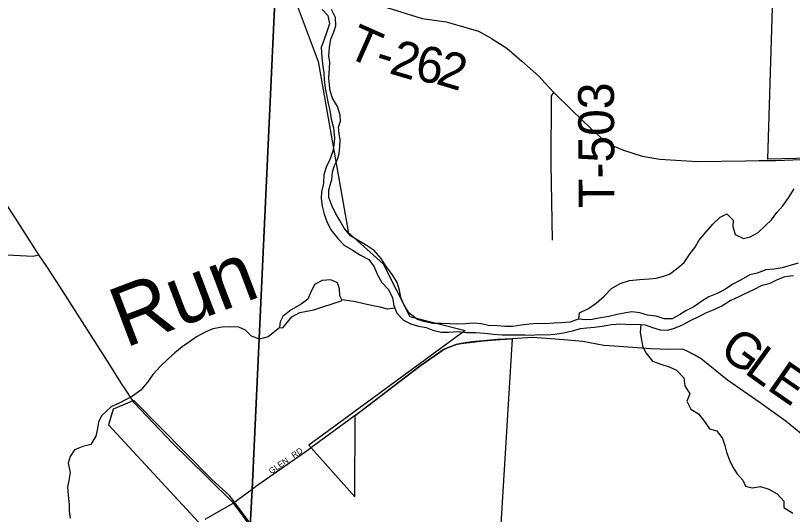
# Model space of a CAD drawing. Extents: x 1759416 to 2214760, y 252598 to 1116833.
# Drawn here: x 1975170 to 1981672, y 862305 to 866477 of the extents above; entities that cross this region are included whole.
import ezdxf

# ---------------------------------------------------------------- set-up
doc = ezdxf.new("R2010")
doc.units = 0
for name, color, linetype in [('GM_X_City_Street', 7, 'Continuous'), ('GM_X_City_Street_Text', 7, 'Continuous'), ('GM_X_Corporation', 7, 'Continuous'), ('GM_X_Major_River', 7, 'Continuous'), ('GM_X_Minor_Lake', 7, 'Continuous'), ('GM_X_Minor_River', 7, 'Continuous'), ('GM_X_Minor_River_Text', 7, 'Continuous'), ('GM_X_State_Route', 7, 'Continuous'), ('GM_X_Township', 7, 'Continuous'), ('GM_X_Township_Road', 7, 'Continuous'), ('GM_X_Township_Road_Text', 7, 'Continuous')]:
    doc.layers.add(name, color=color, linetype=linetype)

msp = doc.modelspace()

# ---------------------------------------------------------------- linework, layer by layer
at = {"layer": 'GM_X_City_Street'}
for points in [[(1973492.8, 864560.1), (1975315.2, 864464.9), (1975365.5, 864474.9)], [(1977670.5, 862880.7), (1977621.5, 862844.7), (1977179.2, 862535.3), (1977150.5, 862514.3), (1976994.5, 862400.2)]]:
    msp.add_lwpolyline(points, dxfattribs=at)
at = {"layer": 'GM_X_Corporation'}
for points in [[(1977201.2, 867433.9), (1977703.7, 866093.8), (1977954.6, 864670.3), (1977948.2, 864668.6), (1978245.5, 864400.9), (1978470.2, 863959.8), (1978933.1, 863844.4), (1977624.9, 862885.5), (1978010.8, 862453.3), (1978013.5, 863132.2), (1978553.3, 863543.7), (1978756.9, 863686.4), (1978856.5, 863726.6), (1978899.6, 863735.5), (1979084.1, 863756.2), (1979224.8, 863766.6), (1979325.1, 863774.1), (1979214, 861950.5)], [(1982067, 865290.6), (1981467.1, 865274.9), (1981506.1, 866543.4)], [(1977179.8, 862167.4), (1976961, 862462.6), (1976811.9, 862597.2), (1976160.8, 863258), (1975987.3, 863186.5), (1975947.8, 863054.3), (1976704, 862236.7)]]:
    msp.add_lwpolyline(points, dxfattribs=at)
at = {"layer": 'GM_X_Major_River'}
for points in [[(1977735.1, 866528.4), (1977783.1, 866476.2), (1977797, 866407.9), (1977774.8, 866339.8), (1977752.6, 866275.6), (1977728.4, 866209.4), (1977732.2, 866125.1), (1977742.1, 866050.9), (1977750, 865998.7), (1977753.9, 865942.5), (1977761.8, 865870.2), (1977771.7, 865814.1), (1977787.6, 865741.8), (1977799.6, 865685.6), (1977811.5, 865609.3), (1977831.4, 865539.1), (1977839.2, 865450.8), (1977835.1, 865392.6), (1977825, 865342.4), (1977800.7, 865272.2), (1977770.5, 865210.1), (1977750.3, 865145.9), (1977747.3, 865079.3)], [(1977816.4, 865103.7), (1977822.6, 865169.9), (1977838.8, 865222), (1977864.9, 865272.2), (1977877.1, 865322.3), (1977883.2, 865380.5), (1977887.4, 865436.6), (1977879.4, 865490.8), (1977873.5, 865543), (1977889.7, 865593.2), (1977887.8, 865645.3), (1977863.8, 865715.6), (1977823.8, 865785.9), (1977803.9, 865846.1), (1977798, 865896.3), (1977792.1, 865952.5), (1977796.3, 866034.7), (1977800.4, 866084.9), (1977792.5, 866141.1), (1977796.6, 866209.3), (1977808.8, 866279.5), (1977831, 866331.6), (1977849.2, 866389.8), (1977847.3, 866460), (1977813.3, 866526.3)], [(1981719.7, 864407.1), (1981651.7, 864387.1), (1981585.7, 864367.2), (1981517.7, 864357.2), (1981447.8, 864349.3), (1981375.8, 864321.4), (1981313.8, 864307.4), (1981243.8, 864267.4), (1981173.8, 864231.5), (1981111.8, 864189.5), (1981041.8, 864151.5), (1980971.8, 864123.5), (1980913.8, 864087.5), (1980847.8, 864041.5), (1980779.8, 864007.5), (1980727.8, 863973.5), (1980663.8, 863939.5), (1980597.9, 863939.6), (1980531.9, 863961.8), (1980458, 863971.9), (1980394.1, 863990), (1980328.1, 863998.2), (1980276.2, 863990.2), (1980206.2, 863978.3), (1980134.2, 863960.3), (1980066.3, 863948.4), (1979996.3, 863934.5), (1979944.3, 863932.6), (1979878.4, 863938.7), (1979810.4, 863912.7), (1979740.4, 863906.8), (1979674.5, 863904.9), (1979610.5, 863898.9), (1979536.6, 863903.1), (1979472.6, 863897.2), (1979402.6, 863887.2), (1979328.7, 863877.3), (1979264.7, 863875.4), (1979200.8, 863881.5), (1979128.8, 863885.6), (1979066.9, 863897.7), (1979002.9, 863903.8), (1978935, 863897.9), (1978863, 863896), (1978805.1, 863900.1), (1978731.1, 863902.2), (1978663.2, 863902.3), (1978599.2, 863914.4), (1978535.3, 863936.6), (1978465.4, 863988.8), (1978423.5, 864055), (1978395.6, 864119.2), (1978383.7, 864181.3), (1978363.8, 864243.5), (1978323.9, 864307.7), (1978272, 864377.9), (1978230.1, 864446.1), (1978172.3, 864512.3), (1978104.4, 864556.5), (1978038.5, 864594.7), (1977974.6, 864634.9), (1977920.7, 864699.1), (1977884.8, 864763.3), (1977848.9, 864825.5), (1977817, 864889.7), (1977793.1, 864955.8), (1977791.7, 865016.9), (1977810.2, 865088.6), (1977816.4, 865103.7)], [(1977747.3, 865079.3), (1977743.2, 865062.1), (1977731.2, 865002), (1977729.1, 864947.9), (1977735, 864881.8), (1977752.9, 864815.6), (1977776.8, 864747.4), (1977810.7, 864683.2), (1977866.6, 864613), (1977922.5, 864554.8), (1977986.4, 864516.6), (1978058.3, 864474.4), (1978126.2, 864436.2), (1978172.1, 864376), (1978198, 864309.8), (1978235.9, 864245.7), (1978291.8, 864187.4), (1978325.7, 864117.2), (1978335.6, 864051.1), (1978361.5, 863988.9), (1978417.4, 863930.7), (1978477.3, 863898.6), (1978543.2, 863878.4), (1978607.2, 863868.3), (1978661.1, 863846.2), (1978733, 863828), (1978797, 863830), (1978869, 863833.9), (1978942.9, 863827.7), (1979022.8, 863825.6), (1979098.8, 863821.5), (1979166.7, 863813.4), (1979242.7, 863807.3), (1979432.5, 863807), (1979484.5, 863804.9), (1979548.4, 863808.8), (1979618.4, 863806.8), (1979682.4, 863812.7), (1979756.3, 863822.6), (1979830.3, 863840.5), (1979898.3, 863860.5), (1979952.2, 863866.4), (1980014.2, 863870.3), (1980080.2, 863878.2), (1980156.1, 863892.2), (1980236.1, 863898.1), (1980312, 863893.9), (1980372, 863895.9), (1980437.9, 863889.8), (1980501.9, 863869.6), (1980565.8, 863847.5), (1980627.7, 863845.4), (1980683.7, 863863.4), (1980751.7, 863889.3), (1980819.7, 863927.3), (1980889.7, 863959.3), (1980947.7, 863991.3), (1981017.7, 864019.2), (1981081.7, 864049.2), (1981149.7, 864093.2), (1981213.7, 864123.2), (1981269.7, 864149.2), (1981349.7, 864185.1), (1981419.6, 864221.1), (1981485.6, 864239), (1981547.6, 864269), (1981611.6, 864295), (1981681.6, 864302.9)]]:
    msp.add_lwpolyline(points, dxfattribs=at)
at = {"layer": 'GM_X_Minor_Lake'}
for points in [[(1977902.5, 864094.6), (1977884.7, 864132.8), (1977881.1, 864193), (1977863.3, 864243.2), (1977809.5, 864265.6), (1977737.4, 864260), (1977673.3, 864228.3), (1977638.9, 864158.3), (1977616.7, 864104.3), (1977560.4, 864064.5), (1977476.2, 864014.8), (1977407.9, 863959.1), (1977383.7, 863915.1), (1977379.5, 863869), (1977407.4, 863864.8), (1977481.9, 863958.7), (1977548.1, 863994.4), (1977666.2, 864015.7)], [(1977666.2, 864015.7), (1977902.5, 864094.6)]]:
    msp.add_lwpolyline(points, dxfattribs=at)
at = {"layer": 'GM_X_Minor_River'}
for points in [[(1979884.7, 863938.1), (1979889.6, 863990.6), (1979965.7, 864026.2), (1980028, 864072), (1980096.3, 864129.8), (1980158.6, 864195.6), (1980230.8, 864237.2), (1980306.9, 864260.9), (1980392.9, 864270.4), (1980472.9, 864273.9), (1980531, 864279.6), (1980585, 864295.3), (1980643.1, 864313), (1980713.4, 864366.8), (1980765.6, 864412.6), (1980816, 864488.5), (1980858.3, 864540.4), (1980888.6, 864596.4), (1980950.9, 864668.2), (1981005.3, 864732.1), (1981067.6, 864791.9), (1981121.7, 864817.6), (1981175.4, 864767.2), (1981173.1, 864713), (1981192.8, 864644.7), (1981262.6, 864612.2), (1981318.6, 864625.9), (1981384.8, 864663.7), (1981443.1, 864717.4), (1981495.4, 864769.3), (1981541.7, 864829.2), (1981589.9, 864885.1), (1981638.3, 864953), (1981686.7, 865028.9)], [(1978344.9, 864028.8), (1978284.1, 864022.1), (1978220.2, 864038.5), (1978162.2, 864048.9), (1978084.4, 864067.4), (1978014.5, 864083.9), (1977944.5, 864094.3), (1977900.2, 864099.6)], [(1977381.7, 863868.7), (1977283.1, 863791.4), (1977213, 863771.7), (1977145.1, 863796.2), (1977093.4, 863846.6), (1977037.5, 863871), (1976961.6, 863873.5), (1976899.6, 863869.8), (1976821.5, 863856.3), (1976763.4, 863832.5), (1976683.2, 863788.9), (1976625, 863749.1), (1976564.8, 863707.3), (1976502.5, 863657.6), (1976448.3, 863605.7), (1976382, 863546), (1976319.6, 863474.1), (1976273.3, 863412.2), (1976218.9, 863344.4), (1976148.7, 863294.6), (1976096.5, 863264.9), (1976038.4, 863235.1), (1975970.2, 863205.4), (1975891.9, 863133.7), (1975865.6, 863079.7), (1975855.3, 863023.6), (1975841, 862959.5), (1975800.6, 862889.5), (1975734.5, 862871.9), (1975662.4, 862846.2), (1975626.1, 862790.3), (1975609.8, 862734.2), (1975627.4, 862655.9), (1975617, 862587.8), (1975604.8, 862533.7), (1975610.4, 862467.5), (1975618, 862389.2), (1975619.7, 862331.1), (1975627.4, 862274.9)], [(1980402.8, 863893), (1980398.6, 863827.1), (1980408.3, 863764.9), (1980418, 863714.7), (1980443.7, 863656.4), (1980499.3, 863587.9), (1980569.1, 863561.4), (1980639, 863538.9), (1980700.9, 863512.5), (1980762.5, 863447.9), (1980772.2, 863381.7), (1980811.8, 863313.2), (1980787.5, 863253.2), (1980821.1, 863184.8), (1980886.9, 863146.3), (1980934.5, 863081.9), (1980976.2, 863021.5), (1981040.1, 863005), (1981085.7, 862940.6), (1981105.4, 862880.3), (1981119.1, 862826.1), (1981144.8, 862757.7), (1981170.5, 862705.4), (1981206.2, 862647.1), (1981255.9, 862592.6), (1981279.6, 862542.3), (1981335.5, 862528), (1981405.5, 862537.6), (1981473.4, 862515.1), (1981545.2, 862476.6), (1981598.9, 862416.1), (1981598.6, 862363.9), (1981676.3, 862315.4)]]:
    msp.add_lwpolyline(points, dxfattribs=at)
at = {"layer": 'GM_X_State_Route'}
for points in [[(1975431.9, 864377.9), (1975365.5, 864474.9), (1975164.5, 864791.7), (1974968.7, 865084.5), (1974773.6, 865392.5), (1974543.2, 865759.6), (1974445.1, 865914.2), (1974302.6, 866066.5), (1974028.4, 866389.5), (1973764.1, 866773.9), (1973334, 867326), (1973203.6, 867497.5)], [(1975540.9, 864211.7), (1975474.5, 864315.7), (1975431.9, 864377.9)], [(1976075.1, 863373.4), (1976071.8, 863378.6), (1975939.5, 863587.3), (1975540.9, 864211.7)], [(1976994.5, 862400.2), (1976774.4, 862617.4), (1976484.4, 862900.6), (1976163.1, 863238.3), (1976075.1, 863373.4)], [(1977777.4, 861576.2), (1977675.6, 861615.2), (1977596.3, 861663.7), (1977492.7, 861733.2), (1977418.9, 861799.4), (1977351.1, 861886.8), (1977267.2, 862012), (1977133.4, 862207.4), (1977072.6, 862296), (1976994.5, 862400.2)]]:
    msp.add_lwpolyline(points, dxfattribs=at)
at = {"layer": 'GM_X_Township'}
for points in [[(1977495.1, 869420.8), (1977468.9, 869117.6), (1977456.6, 868931.3), (1977397.8, 868003.6), (1977388.2, 867910.1), (1977396.5, 867802.9), (1977150.5, 862514.3), (1977133.4, 862207.4), (1977036.1, 860466.3), (1977005.6, 859919.9), (1976964.7, 859186.8), (1976931.3, 858590.2), (1976934.2, 858551.6), (1976926.5, 858367.3), (1976916.9, 858304.6), (1976913.8, 858097.3), (1976901.3, 857970.1), (1976894.3, 857823.9), (1976893.3, 857773.7), (1976896.4, 857732.8), (1976716.8, 854704.7)], [(1976716.8, 854704.7), (1976896.4, 857732.8), (1976893.3, 857773.7), (1976894.3, 857823.9), (1976901.3, 857970.1), (1976913.8, 858097.3), (1976916.9, 858304.6), (1976926.5, 858367.3), (1976934.2, 858551.6), (1976931.3, 858590.2), (1976964.7, 859186.8), (1977005.6, 859919.9), (1977036.1, 860466.3), (1977133.4, 862207.4), (1977150.5, 862514.3), (1977396.5, 867802.9), (1977388.2, 867910.1), (1977397.8, 868003.6), (1977456.6, 868931.3), (1977468.9, 869117.6), (1977495.1, 869420.8)]]:
    msp.add_lwpolyline(points, dxfattribs=at)
at = {"layer": 'GM_X_Township_Road'}
for points in [[(1977631.8, 867201.2), (1977675.8, 867119.1), (1977729.2, 867012.3), (1977820.2, 866881.8), (1977940.7, 866769.1), (1978059.3, 866660.3), (1978233.9, 866559.5), (1978572.4, 866452.5), (1978774.1, 866424.6), (1978872.9, 866396.1), (1979045.5, 866345.8), (1979149.5, 866288.8), (1979153.9, 866285.9)], [(1979153.9, 866285.9), (1979280.2, 866203.3), (1979405.9, 866096), (1979550, 865970.3), (1979603.3, 865912.7)], [(1979603.3, 865912.7), (1979675.7, 865834.5), (1979828.2, 865683.7), (1979984, 865531.1), (1980067.8, 865457.4), (1980178.4, 865383.6), (1980257.2, 865351.7), (1980413.8, 865301.8), (1980563.3, 865276), (1980873.2, 865256.3), (1981277.9, 865262.2), (1981389.2, 865263.8), (1981422.5, 865264.3)], [(1979663.9, 864597.6), (1979653.9, 865239.4), (1979655.6, 865804.4), (1979675.7, 865834.5)], [(1981422.5, 865264.3), (1981532.3, 865265.9), (1982031.3, 865283.5), (1982120.1, 865289.6), (1982155.2, 865292.1)], [(1978950.3, 863741.8), (1978899.6, 863735.5), (1978856.5, 863726.6), (1978756.9, 863686.4), (1978553.3, 863543.7), (1978051.6, 863160.2), (1978013.5, 863132.2), (1977963.2, 863095.3)], [(1979208.3, 863767), (1979204.3, 863766.7), (1979084.1, 863756.1), (1979018.5, 863750.4), (1978950.3, 863741.8)], [(1981758.4, 862967.9), (1981620.4, 863083.6), (1981401.4, 863237.8), (1981129.5, 863428.5), (1980907.9, 863605.4), (1980854, 863637.3), (1980797.6, 863668), (1980751, 863686.4), (1980635.9, 863685.1), (1980487.7, 863688.8), (1980220.5, 863709.4), (1980093.3, 863719.1), (1979917.9, 863750.4), (1979760.3, 863765.3), (1979497.2, 863784.6), (1979325.1, 863774.1), (1979208.3, 863767)], [(1977963.2, 863095.3), (1977670.5, 862880.7)], [(1976994.5, 862400.2), (1976755.2, 862263.9)]]:
    msp.add_lwpolyline(points, dxfattribs=at)

# ---------------------------------------------------------------- texts
at = {"layer": 'GM_X_City_Street_Text'}
for s, rotation, p in [('RD', 34.50504, (1977500.7, 862772.2)), ('GLEN', 34.98957, (1977311.4, 862640.2))]:
    msp.add_text(s, height=50, rotation=rotation, dxfattribs=at).set_placement(p)
at = {"layer": 'GM_X_Minor_River_Text'}
msp.add_text('Run', height=500.03, rotation=20.80874, dxfattribs=at).set_placement((1976087.4, 863696.1))
at = {"layer": 'GM_X_Township_Road_Text'}
for s, rotation, p in [('T', 336.16327, (1977924.7, 866138.7)), ('2', 343.65671, (1978287.6, 865996.3)), ('6', 351.15445, (1978506.7, 865935)), ('-', 342.51021, (1978163.8, 866035.2)), ('2', 343.17465, (1978678.5, 865909)), ('T-503', 90.27315, (1980182.5, 864869.5)), ('G', 324.01896, (1981046.9, 863647.6)), ('L', 324.02908, (1981260.6, 863492.5)), ('E', 325.32535, (1981448.3, 863356.4))]:
    msp.add_text(s, height=300, rotation=rotation, dxfattribs=at).set_placement(p)

doc.saveas('drawing.dxf')
